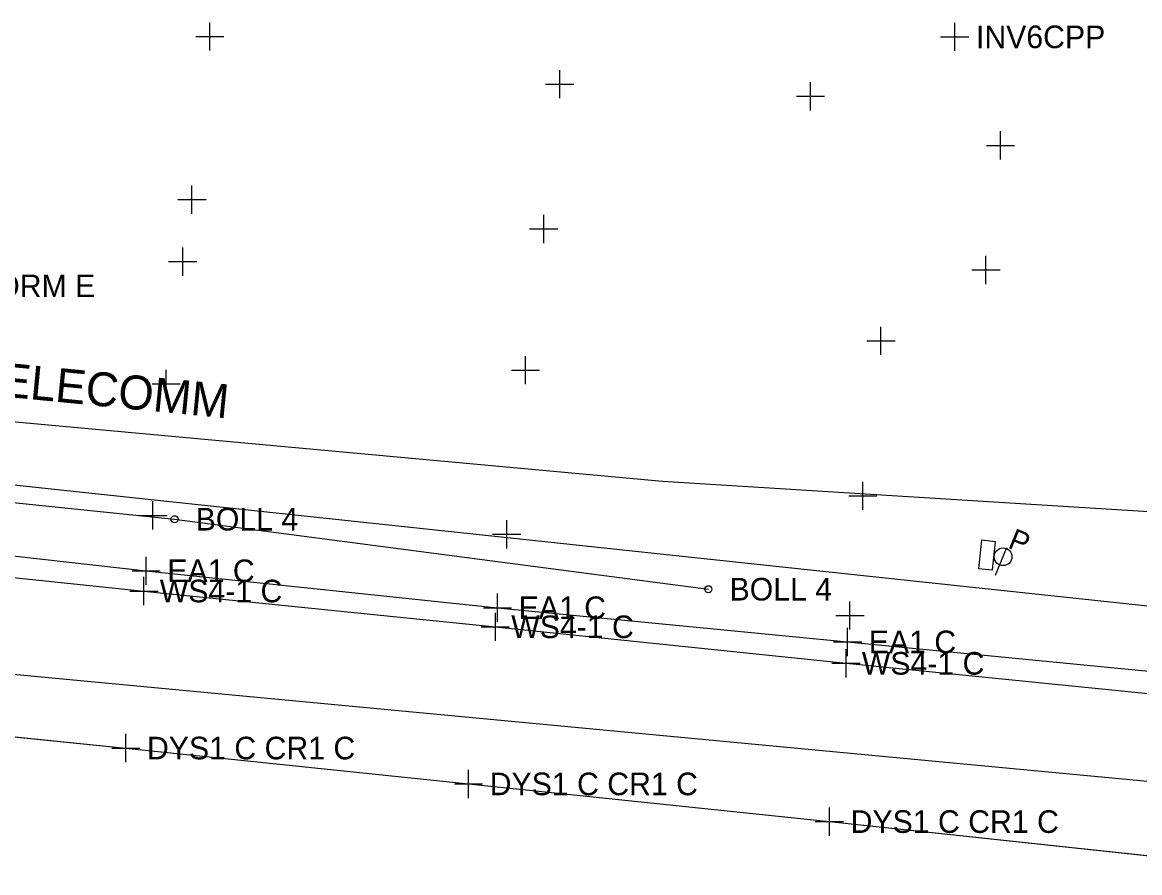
# Model space of a CAD drawing. Extents: x 1363693 to 1365209, y 422201 to 424153.
# Drawn here: x 1363964 to 1364043.1, y 423135.8 to 423196 of the extents above; entities that cross this region are included whole.
import ezdxf

# ---------------------------------------------------------------- set-up
doc = ezdxf.new("R2010")
doc.units = 0
for name, color, linetype in [('O-ALGN-BASELINE-WERK-CL-RW', 7, 'Continuous'), ('OWNERS', 7, 'Continuous'), ('PM_X_Channelizing_Line', 7, 'Continuous'), ('PM_X_CL_Double_Solid', 7, 'Continuous'), ('PM_X_Edge_Line', 7, 'Continuous'), ('RD_X_Misc_Items', 7, 'Continuous'), ('SV_X_Original_Ground', 7, 'Continuous'), ('SV_X_Shot_Marker', 7, 'Continuous'), ('UT_X_Electric_Cells', 7, 'Continuous'), ('UT_X_Telecom_FO', 7, 'Continuous'), ('UT_X_Telecom_Text', 7, 'Continuous'), ('UT_X_Unknown_Cells', 7, 'Continuous'), ('UT_X_Water', 7, 'Continuous')]:
    doc.layers.add(name, color=color, linetype=linetype)

msp = doc.modelspace()

# ---------------------------------------------------------------- linework, layer by layer
at = {"layer": 'O-ALGN-BASELINE-WERK-CL-RW'}
msp.add_lwpolyline([(1363946.375, 423147.199), (1363971.317, 423144.667), (1363995.58, 423142.128), (1364021.135, 423139.461), (1364045.823, 423136.819), (1364070.743, 423134.279), (1364095.743, 423131.549), (1364120.337, 423128.876), (1364145.279, 423126.289), (1364170.549, 423123.503), (1364184.679, 423122.2), (1364194.698, 423121.631), (1364223.029, 423118.455), (1364241.587, 423116.486), (1364258.097, 423114.418), (1364276.821, 423112.152), (1364285.05, 423111.214), (1364289.541, 423110.849), (1364295.586, 423110.248), (1364319.585, 423107.658), (1364345.02, 423104.847), (1364369.674, 423102.16)], dxfattribs=at)
at = {"layer": 'OWNERS'}
msp.add_lwpolyline([(1363798.682, 423175.613), (1363823.663, 423174.201), (1363833.723, 423173.351), (1363848.588, 423171.533), (1363855.604, 423170.527), (1363873.275, 423167.734), (1363898.2, 423165.13), (1363899.452, 423164.968), (1363923.042, 423162.567), (1363933.03, 423161.553), (1363947.981, 423159.993), (1363972.757, 423157.214), (1363997.631, 423154.599), (1364022.422, 423152.18), (1364047.381, 423149.744), (1364072.232, 423147.292), (1364097.055, 423144.216), (1364103.808, 423143.454)], dxfattribs=at)
at = {"layer": 'PM_X_Channelizing_Line'}
for p, q in [((1363947.8, 423158.373), (1363972.601, 423155.781)), ((1363972.601, 423155.781), (1363997.488, 423153.25)), ((1363997.488, 423153.25), (1364022.309, 423150.664)), ((1364022.309, 423150.664), (1364047.252, 423148.162)), ((1363946.375, 423147.199), (1363971.317, 423144.667)), ((1363971.317, 423144.667), (1363995.58, 423142.128)), ((1363995.58, 423142.128), (1364021.135, 423139.461)), ((1364021.135, 423139.461), (1364045.823, 423136.819))]:
    msp.add_line(p, q, dxfattribs=at)
at = {"layer": 'PM_X_CL_Double_Solid'}
for p, q in [((1363946.375, 423147.199), (1363971.317, 423144.667)), ((1363971.317, 423144.667), (1363995.58, 423142.128)), ((1363995.58, 423142.128), (1364021.135, 423139.461)), ((1364021.135, 423139.461), (1364045.823, 423136.819))]:
    msp.add_line(p, q, dxfattribs=at)
at = {"layer": 'PM_X_Edge_Line'}
for p, q in [((1363947.8, 423158.373), (1363972.601, 423155.781)), ((1363972.601, 423155.781), (1363997.488, 423153.25)), ((1363997.488, 423153.25), (1364022.309, 423150.664)), ((1364022.309, 423150.664), (1364047.252, 423148.162))]:
    msp.add_line(p, q, dxfattribs=at)
at = {"layer": 'RD_X_Misc_Items'}
msp.add_lwpolyline([(1363937.261, 423164.746), (1363974.765, 423160.866), (1364012.563, 423155.911)], dxfattribs=at)
msp.add_lwpolyline([(1363937.261, 423164.746), (1363974.765, 423160.866), (1364012.563, 423155.911)], dxfattribs=at)
at = {"layer": 'SV_X_Original_Ground'}
for p, q in [((1363977.265, 423194.037), (1363977.265, 423196.037)), ((1363976.265, 423195.037), (1363978.265, 423195.037)), ((1364002.036, 423190.659), (1364002.036, 423192.659)), ((1364001.036, 423191.659), (1364003.036, 423191.659)), ((1364019.795, 423189.803), (1364019.795, 423191.803)), ((1364018.795, 423190.803), (1364020.795, 423190.803)), ((1364033.247, 423186.325), (1364033.247, 423188.325)), ((1364032.247, 423187.325), (1364034.247, 423187.325)), ((1363975.997, 423182.493), (1363975.997, 423184.493)), ((1363974.997, 423183.493), (1363976.997, 423183.493)), ((1364000.904, 423180.414), (1364000.904, 423182.414)), ((1363999.904, 423181.414), (1364001.904, 423181.414)), ((1363975.348, 423178.097), (1363975.348, 423180.097)), ((1363974.348, 423179.097), (1363976.348, 423179.097)), ((1364032.218, 423177.507), (1364032.218, 423179.507)), ((1364031.218, 423178.507), (1364033.218, 423178.507)), ((1364024.78, 423172.493), (1364024.78, 423174.493)), ((1364023.78, 423173.493), (1364025.78, 423173.493)), ((1363999.614, 423170.415), (1363999.614, 423172.415)), ((1363974.172, 423169.442), (1363974.172, 423171.442)), ((1363998.614, 423171.415), (1364000.614, 423171.415)), ((1363973.172, 423170.442), (1363975.172, 423170.442)), ((1364023.497, 423161.518), (1364023.497, 423163.518)), ((1364022.497, 423162.518), (1364024.497, 423162.518)), ((1363973.235, 423160.138), (1363973.235, 423162.138)), ((1363972.235, 423161.138), (1363974.235, 423161.138)), ((1363998.286, 423158.801), (1363998.286, 423160.801)), ((1363997.286, 423159.801), (1363999.286, 423159.801)), ((1363972.601, 423154.781), (1363972.601, 423156.781)), ((1363971.601, 423155.781), (1363973.601, 423155.781)), ((1364022.583, 423153.05), (1364022.583, 423155.05)), ((1363997.488, 423152.25), (1363997.488, 423154.25)), ((1364021.583, 423154.05), (1364023.583, 423154.05)), ((1363996.488, 423153.25), (1363998.488, 423153.25)), ((1364022.309, 423149.664), (1364022.309, 423151.664)), ((1364021.309, 423150.664), (1364023.309, 423150.664)), ((1363971.317, 423143.667), (1363971.317, 423145.667)), ((1363970.317, 423144.667), (1363972.317, 423144.667)), ((1363995.58, 423141.128), (1363995.58, 423143.128)), ((1363994.58, 423142.128), (1363996.58, 423142.128)), ((1364021.135, 423138.461), (1364021.135, 423140.461)), ((1364020.135, 423139.461), (1364022.135, 423139.461))]:
    msp.add_line(p, q, dxfattribs=at)
at = {"layer": 'SV_X_Shot_Marker'}
for p, q in [((1364030.008, 423194.009), (1364030.008, 423196.009)), ((1364029.008, 423195.009), (1364031.008, 423195.009)), ((1363972.757, 423156.214), (1363972.757, 423158.214)), ((1363971.757, 423157.214), (1363973.757, 423157.214)), ((1363997.631, 423153.599), (1363997.631, 423155.599)), ((1363996.631, 423154.599), (1363998.631, 423154.599)), ((1364022.422, 423151.18), (1364022.422, 423153.18)), ((1364021.422, 423152.18), (1364023.422, 423152.18))]:
    msp.add_line(p, q, dxfattribs=at)
for centre in [(1363974.765, 423160.866), (1364012.563, 423155.911)]:
    msp.add_circle(centre, 0.25, dxfattribs=at)
at = {"layer": 'UT_X_Electric_Cells'}
msp.add_lwpolyline([(1364031.679, 423157.382), (1364032.674, 423157.276), (1364032.887, 423159.264), (1364031.893, 423159.371)], close=True, dxfattribs=at)
msp.add_lwpolyline([(1364031.679, 423157.382), (1364032.674, 423157.276), (1364032.887, 423159.264), (1364031.893, 423159.371)], close=True, dxfattribs=at)
at = {"layer": 'UT_X_Telecom_FO'}
for p, q in [((1363800.763, 423182.733), (1364009.31, 423163.557)), ((1364009.31, 423163.557), (1364083.933, 423158.915))]:
    msp.add_line(p, q, dxfattribs=at)
at = {"layer": 'UT_X_Unknown_Cells'}
msp.add_line((1364032.893, 423156.916), (1364033.696, 423158.861), dxfattribs=at)
msp.add_circle((1364033.427, 423158.21), 0.63, dxfattribs=at)
at = {"layer": 'UT_X_Water'}
for points in [[(1363800.135, 423180.715), (1364166.64, 423141.621), (1364199.33, 423140.767)], [(1363797.978, 423165.496), (1364047.142, 423141.995), (1364047.135, 423142.005), (1364251.213, 423122.543), (1364692.365, 423076.33)]]:
    msp.add_lwpolyline(points, dxfattribs=at)

# ---------------------------------------------------------------- texts
at = {"layer": 'SV_X_Original_Ground'}
for s, p in [('STORMSTRUCTURE4X4 STORM E', (1363934.087, 423176.584)), ('WS4-1 C', (1363973.72, 423154.981)), ('WS4-1 C', (1363998.607, 423152.45)), ('WS4-1 C', (1364023.428, 423149.864)), ('DYS1 C CR1 C', (1363972.817, 423143.867)), ('DYS1 C CR1 C', (1363997.08, 423141.328)), ('DYS1 C CR1 C', (1364022.635, 423138.661))]:
    msp.add_text(s, height=1.6, dxfattribs=at).set_placement(p)
at = {"layer": 'SV_X_Shot_Marker'}
for s, p in [('INV6CPP', (1364031.508, 423194.209)), ('BOLL 4', (1363976.265, 423160.066)), ('EA1 C', (1363974.257, 423156.414)), ('BOLL 4', (1364014.063, 423155.111)), ('EA1 C', (1363999.131, 423153.799)), ('EA1 C', (1364023.922, 423151.38))]:
    msp.add_text(s, height=1.6, dxfattribs=at).set_placement(p)
at = {"layer": 'UT_X_Telecom_Text'}
msp.add_text('EX. TELECOMM', height=2.4, rotation=354.4298, dxfattribs=at).set_placement((1363954.36, 423170.354))
at = {"layer": 'UT_X_Unknown_Cells'}
msp.add_text('P', height=1.503, rotation=337.58271, dxfattribs=at).set_placement((1364033.696, 423158.861))

doc.saveas('drawing.dxf')
